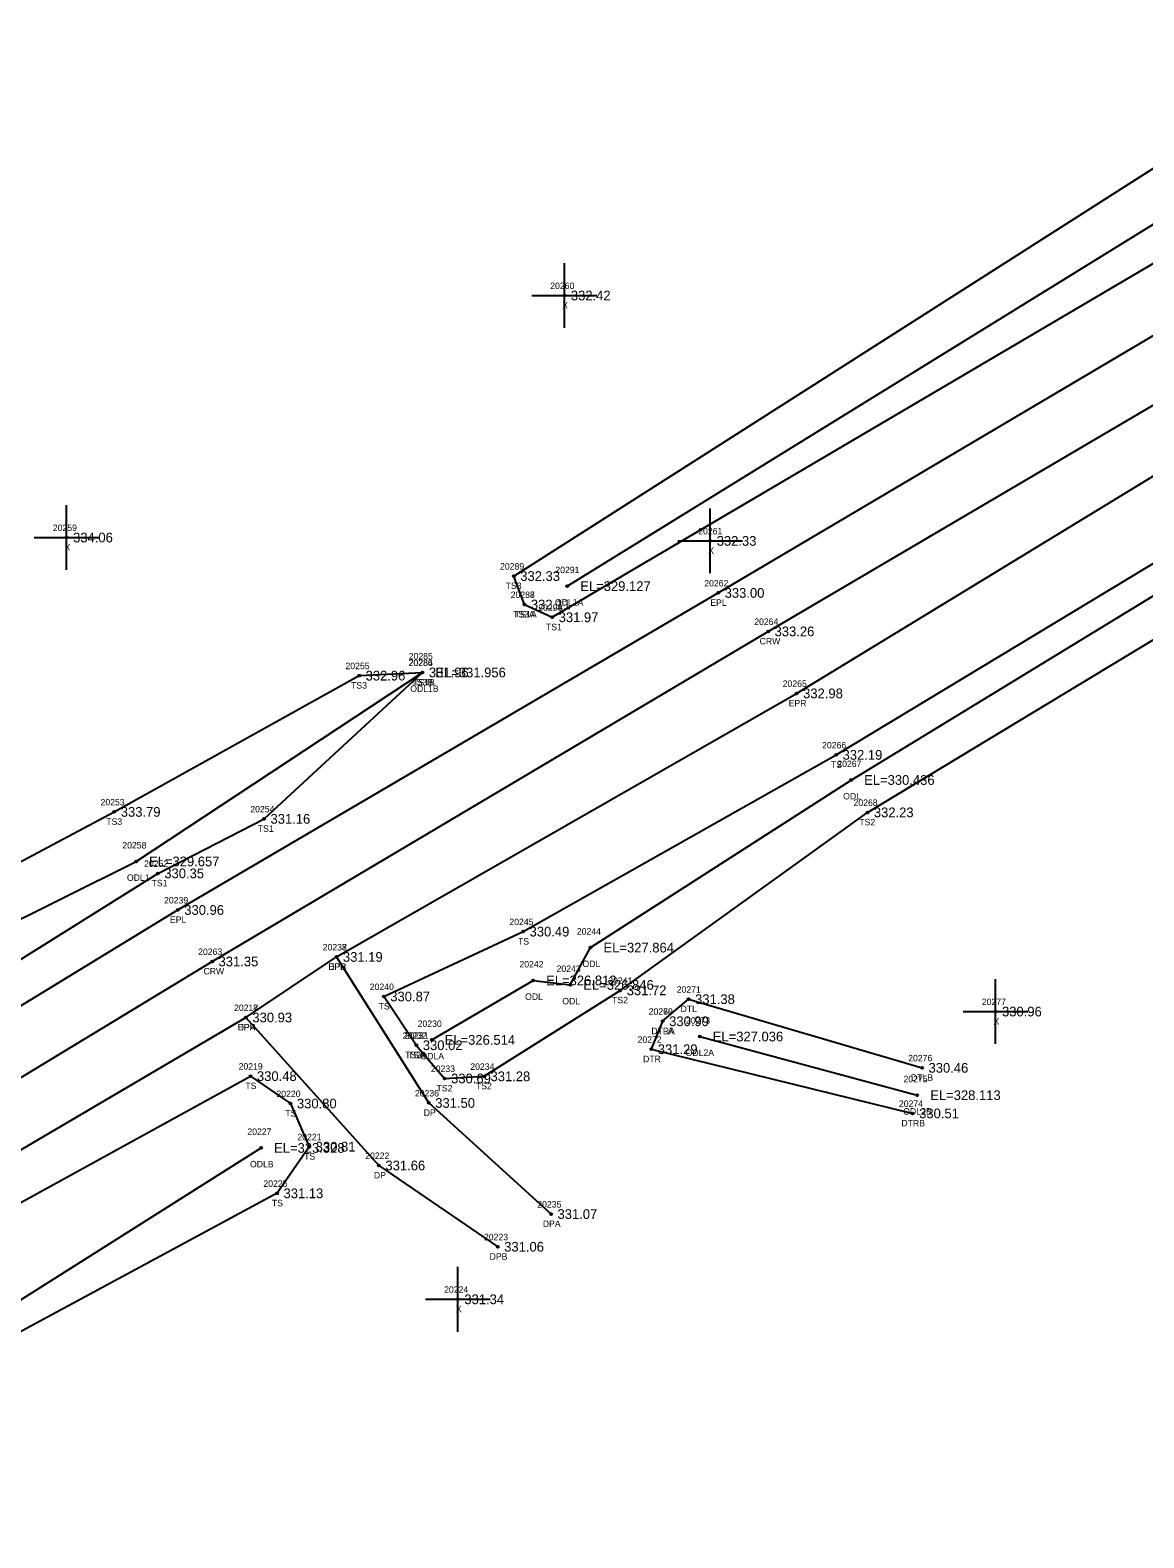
# Model space of a CAD drawing. Extents: x 2231109 to 2232328, y 1035718 to 1036919.
# Drawn here: x 2231658.8 to 2231830.7, y 1036422.9 to 1036655.6 of the extents above; entities that cross this region are included whole.
import ezdxf

# ---------------------------------------------------------------- set-up
doc = ezdxf.new("R2010")
doc.units = 0
for name, color, linetype in [('RD_DTM_BkLn1', 7, 'Continuous'), ('RD_DTM_BkLn2', 7, 'Continuous'), ('RD_DTM_BkLn_txCode', 7, 'Continuous'), ('RD_EX_Driveway', 7, 'Continuous'), ('RD_EX_Driveway_txCode', 7, 'Continuous'), ('RD_EX_H2O', 7, 'Continuous'), ('RD_EX_H2O_txCode', 7, 'Continuous'), ('RD_EX_Misc', 7, 'Continuous'), ('RD_EX_Misc_txCode', 7, 'Continuous'), ('RD_EX_Road', 7, 'Continuous'), ('RD_EX_Road_txCode', 7, 'Continuous'), ('RD_EX_TX_Driveway_ELEV', 7, 'Continuous'), ('RD_EX_TX_H2O_ELEV', 7, 'Continuous'), ('RD_EX_TX_Misc_ELEV', 7, 'Continuous'), ('RD_EX_TX_Road_ELEV', 7, 'Continuous'), ('RD_HC_Survey_ELEV', 7, 'Continuous'), ('RD_HC_Survey_txCode', 7, 'Continuous'), ('RD_SMD_Locator', 7, 'Continuous')]:
    doc.layers.add(name, color=color, linetype=linetype)

msp = doc.modelspace()

# ---------------------------------------------------------------- linework, layer by layer
at = {"layer": 'RD_DTM_BkLn1'}
msp.add_lwpolyline([(2231606.1, 1036462.92), (2231686.87, 1036511.89), (2231772.7, 1036562.84), (2231856.39, 1036612), (2231941.22, 1036662.52), (2232026.21, 1036712.41), (2232112.3, 1036762.07), (2232195.17, 1036811.63), (2232281.68, 1036862.71)], dxfattribs=at)
at = {"layer": 'RD_DTM_BkLn2'}
for points in [[(2231735.08, 1036566.99), (2231733.44, 1036571.38), (2231838.97, 1036638.65), (2231923.32, 1036688.26), (2232007.46, 1036737.64), (2232093.05, 1036790.84), (2232175.73, 1036838.16), (2232263.96, 1036889.44)], [(2231735.08, 1036566.99), (2231739.37, 1036565.02), (2231846.03, 1036627.82), (2231929.8, 1036677.63), (2232016.53, 1036728.58), (2232102.07, 1036778.24), (2232186.07, 1036826.97), (2232269.67, 1036876.59)], [(2231718.4, 1036498.96), (2231713.38, 1036506.48), (2231734.88, 1036516.5), (2231783.19, 1036543.78), (2231867.56, 1036594.75), (2232035.39, 1036697.6), (2232204.37, 1036795.95), (2232291.91, 1036847.83)], [(2231718.4, 1036498.96), (2231722.77, 1036493.83), (2231728.85, 1036494.16), (2231749.87, 1036507.43), (2231788.02, 1036534.9), (2231874.52, 1036587.15), (2231959.93, 1036637.18), (2232042.1, 1036685.84), (2232133.02, 1036735.49), (2232212.03, 1036786.36), (2232298.34, 1036837.91)], [(2231573.22, 1036475.66), (2231594.27, 1036493.73), (2231671.78, 1036534.98), (2231709.57, 1036556.01), (2231719.34, 1036556.5)], [(2231577.44, 1036470.88), (2231599.69, 1036476.13), (2231678.5, 1036525.49), (2231694.89, 1036533.9), (2231719.34, 1036556.5)], [(2231593.79, 1036430.95), (2231605.6, 1036444.4), (2231613.9, 1036450.83), (2231692.8, 1036494.19), (2231698.97, 1036489.96), (2231701.87, 1036483.3), (2231696.9, 1036476.1), (2231598.32, 1036422.92)]]:
    msp.add_lwpolyline(points, dxfattribs=at)
at = {"layer": 'RD_EX_Driveway'}
for points in [[(2231739.19, 1036472.9), (2231720.32, 1036490.05), (2231706.07, 1036512.59)], [(2231692.09, 1036503.24), (2231712.63, 1036480.4), (2231730.96, 1036467.85)]]:
    msp.add_lwpolyline(points, dxfattribs=at)
at = {"layer": 'RD_EX_H2O'}
msp.add_line((2231762.15, 1036500.3), (2231795.72, 1036491.25), dxfattribs=at)
for points in [[(2231741.7, 1036569.83), (2231843.08, 1036632.45), (2231926.34, 1036681.31), (2232011.09, 1036733.11), (2232099.56, 1036784.62), (2232183.31, 1036833.18), (2232266.22, 1036880.93)], [(2231720.77, 1036499.78), (2231736.43, 1036508.96), (2231742.17, 1036508.27), (2231745.29, 1036514.03), (2231785.52, 1036539.9), (2231869.59, 1036591.16), (2232038.46, 1036693), (2232129.43, 1036745.26), (2232207.65, 1036791.56), (2232294.95, 1036842.48)], [(2231574.37, 1036473.02), (2231594.18, 1036487.03), (2231675.14, 1036527.33), (2231719.34, 1036556.5)], [(2231756.42, 1036502.66), (2231760.43, 1036506.07), (2231796.46, 1036495.47)], [(2231756.42, 1036502.66), (2231754.67, 1036498.34), (2231795.01, 1036488.44)], [(2231595.07, 1036425.7), (2231623.2, 1036438.12), (2231694.44, 1036483.11)]]:
    msp.add_lwpolyline(points, dxfattribs=at)
at = {"layer": 'RD_EX_Misc'}
for p, q in [((2231741.25, 1036609.69), (2231741.25, 1036619.69)), ((2231736.25, 1036614.69), (2231746.25, 1036614.69)), ((2231664.42, 1036572.33), (2231664.42, 1036582.33)), ((2231763.76, 1036571.81), (2231763.76, 1036581.81)), ((2231659.42, 1036577.33), (2231669.42, 1036577.33)), ((2231758.76, 1036576.81), (2231768.76, 1036576.81)), ((2231807.8, 1036499.16), (2231807.8, 1036509.16)), ((2231802.8, 1036504.16), (2231812.8, 1036504.16)), ((2231724.81, 1036454.74), (2231724.81, 1036464.74)), ((2231719.81, 1036459.74), (2231729.81, 1036459.74))]:
    msp.add_line(p, q, dxfattribs=at)
at = {"layer": 'RD_EX_Road'}
for points in [[(2231606.1, 1036462.92), (2231601.27, 1036470.82), (2231681.58, 1036519.84), (2231764.99, 1036568.78), (2231851.5, 1036619.95), (2231935.62, 1036669.65), (2232021.78, 1036720.22), (2232106.75, 1036770.57), (2232190.54, 1036819.2), (2232275.92, 1036870.27)], [(2231606.1, 1036462.92), (2231610.57, 1036455.36), (2231692.09, 1036503.24), (2231706.07, 1036512.59), (2231777.1, 1036553.27), (2231861.39, 1036604.65), (2231946.39, 1036654.77), (2232031.07, 1036704.2), (2232117.06, 1036755.16), (2232199.91, 1036803.8), (2232286.7, 1036855.36)]]:
    msp.add_lwpolyline(points, dxfattribs=at)
at = {"layer": 'RD_SMD_Locator'}
for centre in [(2231741.25, 1036614.69), (2231664.42, 1036577.33), (2231763.76, 1036576.81), (2231733.44, 1036571.38), (2231741.7, 1036569.83), (2231735.08, 1036566.99), (2231735.08, 1036566.99), (2231764.99, 1036568.78), (2231739.37, 1036565.02), (2231772.7, 1036562.84), (2231709.57, 1036556.01), (2231719.34, 1036556.5), (2231719.34, 1036556.5), (2231719.34, 1036556.5), (2231777.1, 1036553.27), (2231783.19, 1036543.78), (2231785.52, 1036539.9), (2231671.78, 1036534.98), (2231788.02, 1036534.9), (2231694.89, 1036533.9), (2231675.14, 1036527.33), (2231678.5, 1036525.49), (2231681.58, 1036519.84), (2231734.88, 1036516.5), (2231745.29, 1036514.03), (2231686.87, 1036511.89), (2231706.07, 1036512.59), (2231706.07, 1036512.59), (2231736.43, 1036508.96), (2231713.38, 1036506.48), (2231742.17, 1036508.27), (2231749.87, 1036507.43), (2231760.43, 1036506.07), (2231807.8, 1036504.16), (2231692.09, 1036503.24), (2231692.09, 1036503.24), (2231756.42, 1036502.66), (2231756.42, 1036502.66), (2231720.77, 1036499.78), (2231762.15, 1036500.3), (2231718.4, 1036498.96), (2231718.4, 1036498.96), (2231754.67, 1036498.34), (2231796.46, 1036495.47), (2231692.8, 1036494.19), (2231722.77, 1036493.83), (2231728.85, 1036494.16), (2231795.72, 1036491.25), (2231698.97, 1036489.96), (2231720.32, 1036490.05), (2231795.01, 1036488.44), (2231701.87, 1036483.3), (2231694.44, 1036483.11), (2231712.63, 1036480.4), (2231696.9, 1036476.1), (2231739.19, 1036472.9), (2231730.96, 1036467.85), (2231724.81, 1036459.74)]:
    msp.add_circle(centre, 0.15, dxfattribs=at)

# ---------------------------------------------------------------- texts
at = {"layer": 'RD_DTM_BkLn_txCode'}
for s, p in [('20289', (2231731.32, 1036572.38)), ('TS3', (2231732.19, 1036569.38)), ('20287', (2231732.96, 1036567.99)), ('20288', (2231732.96, 1036567.99)), ('TS3A', (2231733.34, 1036564.99)), ('TS1A', (2231733.63, 1036564.99)), ('20290', (2231737.22, 1036566.02)), ('TS1', (2231738.41, 1036563.02)), ('20255', (2231707.46, 1036557.01)), ('20286', (2231717.2, 1036557.5)), ('20284', (2231717.23, 1036557.5)), ('TS3B', (2231717.63, 1036554.5)), ('TS1B', (2231717.91, 1036554.5)), ('TS3', (2231708.33, 1036554.01)), ('20266', (2231781.03, 1036544.78)), ('TS', (2231782.4, 1036541.78)), ('20253', (2231669.66, 1036535.98)), ('20268', (2231785.88, 1036535.9)), ('20254', (2231692.77, 1036534.9)), ('TS3', (2231670.54, 1036532.98)), ('TS1', (2231693.92, 1036531.9)), ('TS2', (2231786.78, 1036532.9)), ('20252', (2231676.38, 1036526.49)), ('TS1', (2231677.54, 1036523.49)), ('20245', (2231732.76, 1036517.5)), ('TS', (2231734.09, 1036514.5)), ('20241', (2231748.03, 1036508.43)), ('20240', (2231711.22, 1036507.48)), ('TS', (2231712.58, 1036504.48)), ('TS2', (2231748.62, 1036505.43)), ('20232', (2231716.29, 1036499.96)), ('20231', (2231716.57, 1036499.96)), ('TS2A', (2231716.67, 1036496.96)), ('TSA', (2231717.12, 1036496.96)), ('20219', (2231690.97, 1036495.19)), ('20233', (2231720.65, 1036494.83)), ('20234', (2231726.73, 1036495.16)), ('TS', (2231692.01, 1036492.19)), ('TS2', (2231721.52, 1036491.83)), ('TS2', (2231727.6, 1036492.16)), ('20220', (2231696.81, 1036490.96)), ('TS', (2231698.17, 1036487.96)), ('20221', (2231700.04, 1036484.3)), ('TS', (2231701.08, 1036481.3)), ('20225', (2231694.79, 1036477.1)), ('TS', (2231696.11, 1036474.1))]:
    msp.add_text(s, height=1, dxfattribs=at).set_placement(p)
at = {"layer": 'RD_EX_Driveway_txCode'}
for s, p in [('20237', (2231703.95, 1036513.59)), ('DPB', (2231704.82, 1036510.59)), ('20218', (2231690.26, 1036504.24)), ('DPA', (2231690.83, 1036501.24)), ('20236', (2231718.18, 1036491.05)), ('DP', (2231719.54, 1036488.05)), ('20222', (2231710.51, 1036481.4)), ('DP', (2231711.85, 1036478.4)), ('20235', (2231737.07, 1036473.9)), ('DPA', (2231737.92, 1036470.9)), ('20223', (2231728.84, 1036468.85)), ('DPB', (2231729.71, 1036465.85))]:
    msp.add_text(s, height=1, dxfattribs=at).set_placement(p)
at = {"layer": 'RD_EX_H2O_txCode'}
for s, p in [('20291', (2231739.86, 1036571.83)), ('ODL1A', (2231739.8, 1036566.83)), ('20285', (2231717.23, 1036558.5)), ('ODL1B', (2231717.46, 1036553.5)), ('20267', (2231783.38, 1036541.9)), ('ODL', (2231784.28, 1036536.9)), ('20258', (2231673.02, 1036529.33)), ('ODL1', (2231673.73, 1036524.33)), ('20244', (2231743.18, 1036516.03)), ('20242', (2231734.31, 1036510.96)), ('20243', (2231740.05, 1036510.27)), ('ODL', (2231744.05, 1036511.03)), ('ODL', (2231735.19, 1036505.96)), ('20271', (2231758.59, 1036507.07)), ('ODL', (2231740.93, 1036505.27)), ('20270', (2231754.26, 1036503.66)), ('20269', (2231754.27, 1036503.66)), ('DTL', (2231759.18, 1036504.07)), ('20230', (2231718.61, 1036501.78)), ('20273', (2231760.03, 1036502.3)), ('20272', (2231752.55, 1036499.34)), ('DTRA', (2231754.66, 1036500.66)), ('DTLA', (2231754.68, 1036500.66)), ('ODLA', (2231719.04, 1036496.78)), ('DTR', (2231753.4, 1036496.34)), ('ODL2A', (2231759.97, 1036497.3)), ('20276', (2231794.32, 1036496.47)), ('20275', (2231793.6, 1036493.25)), ('DTLB', (2231794.74, 1036493.47)), ('20274', (2231792.89, 1036489.44)), ('ODL2B', (2231793.55, 1036488.25)), ('20227', (2231692.32, 1036485.11)), ('DTRB', (2231793.27, 1036486.44)), ('ODLB', (2231692.73, 1036480.11))]:
    msp.add_text(s, height=1, dxfattribs=at).set_placement(p)
at = {"layer": 'RD_EX_Misc_txCode'}
for s, p in [('20260', (2231739.07, 1036615.69)), ('X', (2231740.93, 1036612.69)), ('20259', (2231662.3, 1036578.33)), ('20261', (2231761.91, 1036577.81)), ('X', (2231664.1, 1036575.33)), ('X', (2231763.45, 1036574.81)), ('20277', (2231805.69, 1036505.16)), ('X', (2231807.49, 1036502.16)), ('20224', (2231722.69, 1036460.74)), ('X', (2231724.5, 1036457.74))]:
    msp.add_text(s, height=1, dxfattribs=at).set_placement(p)
at = {"layer": 'RD_EX_Road_txCode'}
for s, p in [('20262', (2231762.84, 1036569.78)), ('EPL', (2231763.78, 1036566.78)), ('20265', (2231774.95, 1036554.27)), ('EPR', (2231775.87, 1036551.27)), ('20239', (2231679.46, 1036520.84)), ('EPL', (2231680.37, 1036517.84)), ('20238', (2231703.95, 1036513.59)), ('EPR', (2231704.84, 1036510.59)), ('20217', (2231690.26, 1036504.24)), ('EPR', (2231690.87, 1036501.24))]:
    msp.add_text(s, height=1, dxfattribs=at).set_placement(p)
at = {"layer": 'RD_EX_TX_Driveway_ELEV'}
for s, p in [('331.19', (2231707.07, 1036511.84)), ('330.93', (2231693.09, 1036502.49)), ('331.50', (2231721.32, 1036489.3)), ('331.66', (2231713.63, 1036479.65)), ('331.07', (2231740.19, 1036472.15)), ('331.06', (2231731.96, 1036467.1))]:
    msp.add_text(s, height=1.5, dxfattribs=at).set_placement(p)
at = {"layer": 'RD_EX_TX_H2O_ELEV'}
for s, p in [('EL=329.127', (2231743.7, 1036569.08)), ('EL=331.956', (2231721.34, 1036555.75)), ('EL=330.436', (2231787.52, 1036539.15)), ('EL=329.657', (2231677.14, 1036526.58)), ('EL=327.864', (2231747.29, 1036513.28)), ('EL=326.812', (2231738.43, 1036508.21)), ('EL=326.846', (2231744.17, 1036507.52)), ('331.38', (2231761.43, 1036505.32)), ('330.99', (2231757.42, 1036501.91)), ('330.99', (2231757.42, 1036501.91)), ('EL=326.514', (2231722.77, 1036499.03)), ('EL=327.036', (2231764.15, 1036499.55)), ('331.29', (2231755.67, 1036497.59)), ('330.46', (2231797.46, 1036494.72)), ('EL=328.113', (2231797.72, 1036490.5)), ('330.51', (2231796.01, 1036487.69)), ('EL=323.328', (2231696.44, 1036482.36))]:
    msp.add_text(s, height=1.5, dxfattribs=at).set_placement(p)
at = {"layer": 'RD_EX_TX_Misc_ELEV'}
for s, p in [('332.42', (2231742.25, 1036613.94)), ('334.06', (2231665.42, 1036576.58)), ('332.33', (2231764.76, 1036576.06)), ('332.33', (2231734.44, 1036570.63)), ('332.11', (2231736.08, 1036566.24)), ('332.11', (2231736.08, 1036566.24)), ('331.97', (2231740.37, 1036564.27)), ('332.96', (2231710.57, 1036555.26)), ('331.96', (2231720.34, 1036555.75)), ('331.96', (2231720.34, 1036555.75)), ('332.19', (2231784.19, 1036543.03)), ('333.79', (2231672.78, 1036534.23)), ('331.16', (2231695.89, 1036533.15)), ('332.23', (2231789.02, 1036534.15)), ('330.35', (2231679.5, 1036524.74)), ('330.49', (2231735.88, 1036515.75)), ('330.87', (2231714.38, 1036505.73)), ('331.72', (2231750.87, 1036506.68)), ('330.96', (2231808.8, 1036503.41)), ('330.02', (2231719.4, 1036498.21)), ('330.02', (2231719.4, 1036498.21)), ('330.48', (2231693.8, 1036493.44)), ('331.28', (2231729.85, 1036493.41)), ('330.69', (2231723.77, 1036493.08)), ('330.80', (2231699.97, 1036489.21)), ('330.81', (2231702.87, 1036482.55)), ('331.13', (2231697.9, 1036475.35)), ('331.34', (2231725.81, 1036458.99))]:
    msp.add_text(s, height=1.5, dxfattribs=at).set_placement(p)
at = {"layer": 'RD_EX_TX_Road_ELEV'}
for s, p in [('333.00', (2231765.99, 1036568.03)), ('332.98', (2231778.1, 1036552.52)), ('330.96', (2231682.58, 1036519.09)), ('331.19', (2231707.07, 1036511.84)), ('330.93', (2231693.09, 1036502.49))]:
    msp.add_text(s, height=1.5, dxfattribs=at).set_placement(p)
at = {"layer": 'RD_HC_Survey_ELEV'}
for s, p in [('333.26', (2231773.7, 1036562.09)), ('331.35', (2231687.87, 1036511.14))]:
    msp.add_text(s, height=1.5, dxfattribs=at).set_placement(p)
at = {"layer": 'RD_HC_Survey_txCode'}
for s, p in [('20264', (2231770.56, 1036563.84)), ('CRW', (2231771.39, 1036560.84)), ('20263', (2231684.72, 1036512.89)), ('CRW', (2231685.55, 1036509.89))]:
    msp.add_text(s, height=1, dxfattribs=at).set_placement(p)

doc.saveas('drawing.dxf')
